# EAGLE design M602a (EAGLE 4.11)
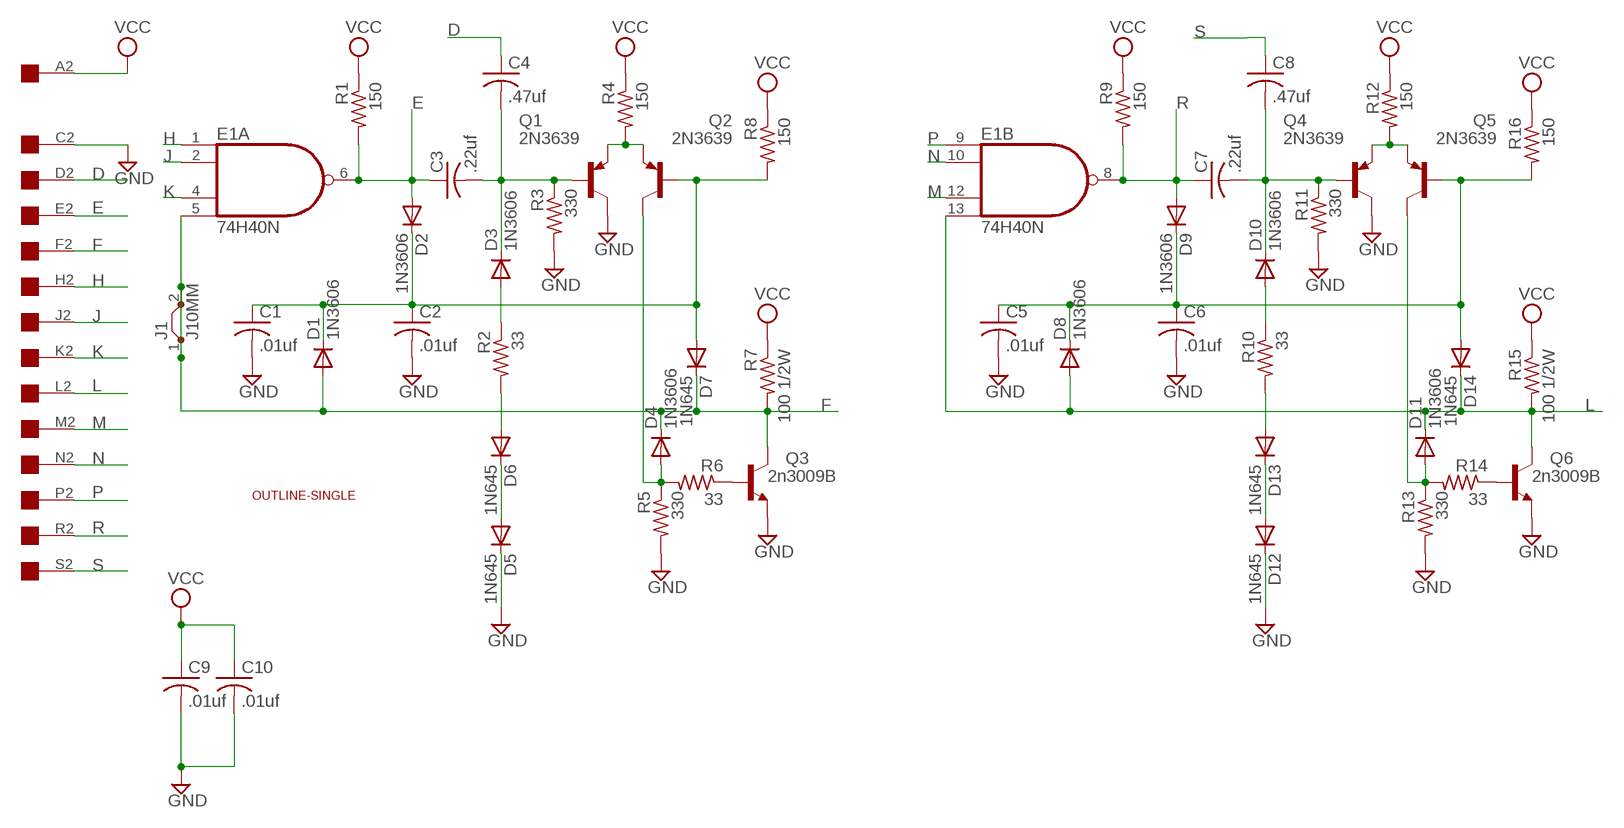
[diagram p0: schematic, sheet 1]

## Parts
C1  .01uf  C-US050-025X075  [C050-025X075]
C2  .01uf  C-US050-025X075  [C050-025X075]
C3  .22uf  C-US050-025X075  [C050-025X075]
C4  .47uf  C-US050-025X075  [C050-025X075]
C5  .01uf  C-US050-025X075  [C050-025X075]
C6  .01uf  C-US050-025X075  [C050-025X075]
C7  .22uf  C-US050-025X075  [C050-025X075]
C8  .47uf  C-US050-025X075  [C050-025X075]
C9  .01uf  C-US050-025X075  [C050-025X075]
C10  .01uf  C-US050-025X075  [C050-025X075]
D1  1N3606  1N4004  [DO41-10]
D2  1N3606  1N4004  [DO41-10]
D3  1N3606  1N4004  [DO41-10]
D4  1N3606  1N4004  [DO41-10]
D5  1N645  1N4004  [DO41-10]
D6  1N645  1N4004  [DO41-10]
D7  1N645  1N4004  [DO41-10]
D8  1N3606  1N4004  [DO41-10]
D9  1N3606  1N4004  [DO41-10]
D10  1N3606  1N4004  [DO41-10]
D11  1N3606  1N4004  [DO41-10]
D12  1N645  1N4004  [DO41-10]
D13  1N645  1N4004  [DO41-10]
D14  1N645  1N4004  [DO41-10]
E1  74H40N  74LS20N  [DIL14]
J1  J10MM  [10]
Q1  2N3639  2N5415  [TO39]
Q2  2N3639  2N5415  [TO39]
Q3  2n3009B  2N1711  [TO39]
Q4  2N3639  2N5415  [TO39]
Q5  2N3639  2N5415  [TO39]
Q6  2n3009B  2N1711  [TO39]
R1  150  R-US_0207/10  [0207/10]
R2  33  R-US_0207/10  [0207/10]
R3  330  R-US_0207/10  [0207/10]
R4  150  R-US_0207/10  [0207/10]
R5  330  R-US_0207/10  [0207/10]
R6  33  R-US_0207/10  [0207/10]
R7  100 1/2W  R-US_0207/10  [0207/10]
R8  150  R-US_0207/10  [0207/10]
R9  150  R-US_0207/10  [0207/10]
R10  33  R-US_0207/10  [0207/10]
R11  330  R-US_0207/10  [0207/10]
R12  150  R-US_0207/10  [0207/10]
R13  330  R-US_0207/10  [0207/10]
R14  33  R-US_0207/10  [0207/10]
R15  100 1/2W  R-US_0207/10  [0207/10]
R16  150  R-US_0207/10  [0207/10]
U$1  EDGE-1  [EDGE-CON1]
U$2  OUTLINE-SINGLE  [SINGLE]

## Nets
D: C4.1 U$1.D2
E: C3.1 D2.A E1.6(A:O) R1.2 U$1.E2
F: D1.A D4.C D7.C E1.5(A:I3) J1.1 J1.2 Q3.3(C) R7.2 U$1.F2
GND: C1.2 C2.2 C5.2 C6.2 C9.2 C10.2 D5.C D12.C Q1.3(C) Q3.1(E) Q4.3(C) Q6.1(E) R3.2 R5.2 R11.2 R13.2 U$1.C2
H: E1.1(A:I0) U$1.H2
J: E1.2(A:I1) U$1.J2
K: E1.4(A:I2) U$1.K2
L: D8.A D11.C D14.C E1.13(B:I3) Q6.3(C) R15.2 U$1.L2
M: E1.12(B:I2) U$1.M2
N: E1.10(B:I1) U$1.N2
N$1: C1.1 C2.1 D1.C D2.C D7.A Q2.2(B) R8.2
N$2: D3.A R2.1
N$3: D10.A R10.1
N$4: C3.2 C4.2 D3.C Q1.2(B) R3.1
N$5: Q1.1(E) Q2.1(E) R4.2
N$6: D4.A Q2.3(C) R5.1 R6.2
N$7: Q3.2(B) R6.1
N$8: D6.A R2.2
N$9: D5.A D6.C
N$10: C7.2 C8.2 D10.C Q4.2(B) R11.1
N$11: C5.1 C6.1 D8.C D9.C D14.A Q5.2(B) R16.2
N$13: D13.A R10.2
N$14: D12.A D13.C
N$15: Q6.2(B) R14.1
N$16: Q4.1(E) Q5.1(E) R12.2
N$17: D11.A Q5.3(C) R13.1 R14.2
P: E1.9(B:I0) U$1.P2
R: C7.1 D9.A E1.8(B:O) R9.2 U$1.R2
S: C8.1 U$1.S2
VCC: C9.1 C10.1 R1.1 R4.1 R7.1 R8.1 R9.1 R12.1 R15.1 R16.1 U$1.A2
Unconnected: U$1.B2 U$1.T2 U$1.U2 U$1.V2

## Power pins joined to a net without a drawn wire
GND: E1.7(P:GND)
VCC: E1.14(P:VCC)

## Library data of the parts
C1-C10 = rcl:C-US: CAPACITOR, American symbol
D1-D14 = diode:1N4004: DIODE
E1 = 74xx-us:74*20: Dual 4-input NAND gate
J1 = jumper:J: Bridge
Q1 Q2 Q4 Q5 = transistor-pnp:2N5415*: PNP Transistror
Q3 Q6 = transistor-npn:2N1711: NPN Transistor
R1-R16 = rcl:R-US_: RESISTOR, American symbol
U$1 = dec-con:EDGE-1: Single-Sided DEC Edge Connector -- (side 2)
U$2 = dec-con:OUTLINE-*: Board outlines for DEC boards.

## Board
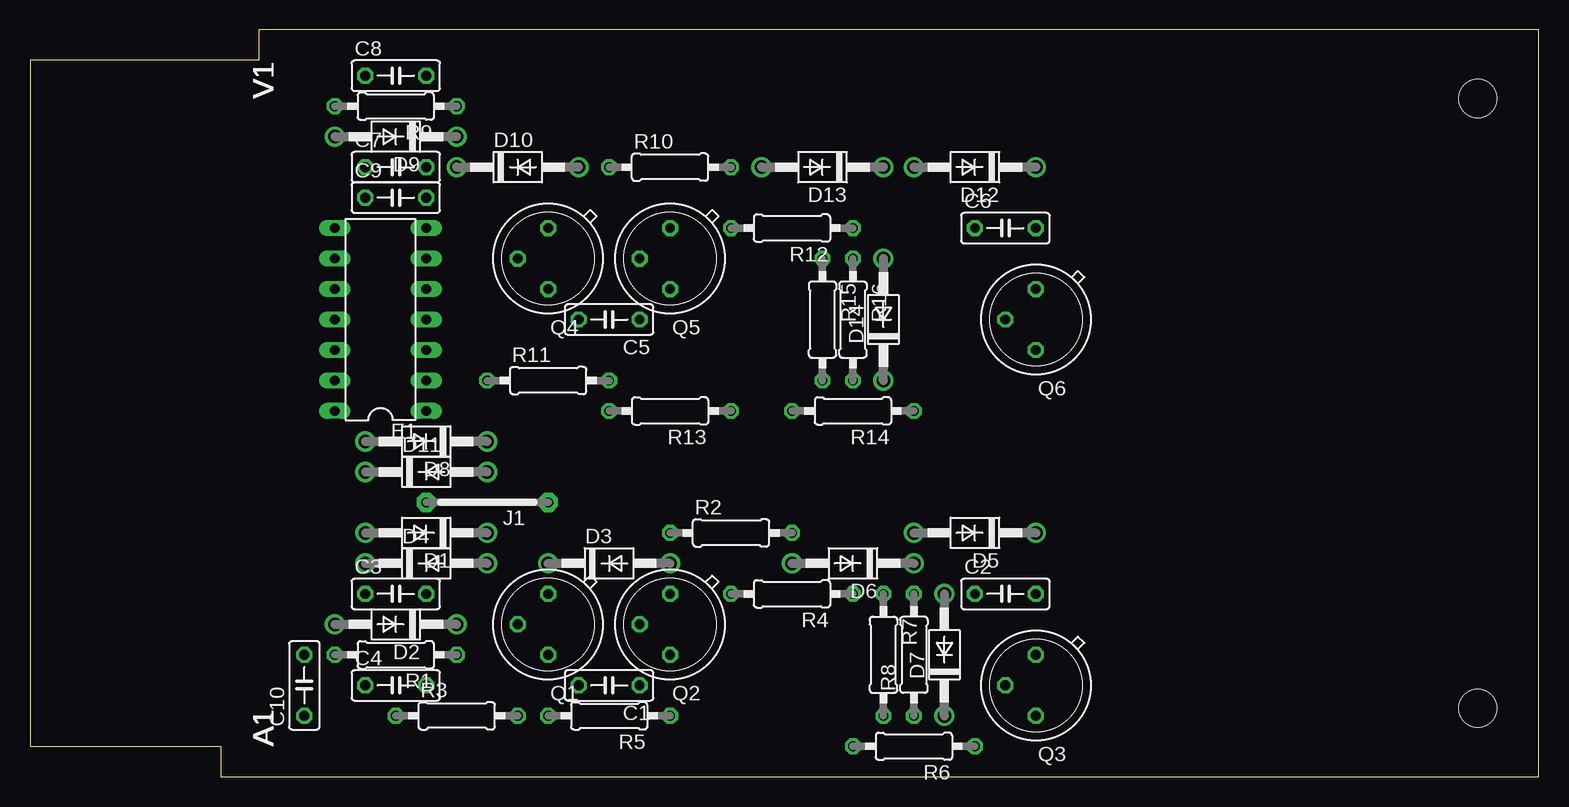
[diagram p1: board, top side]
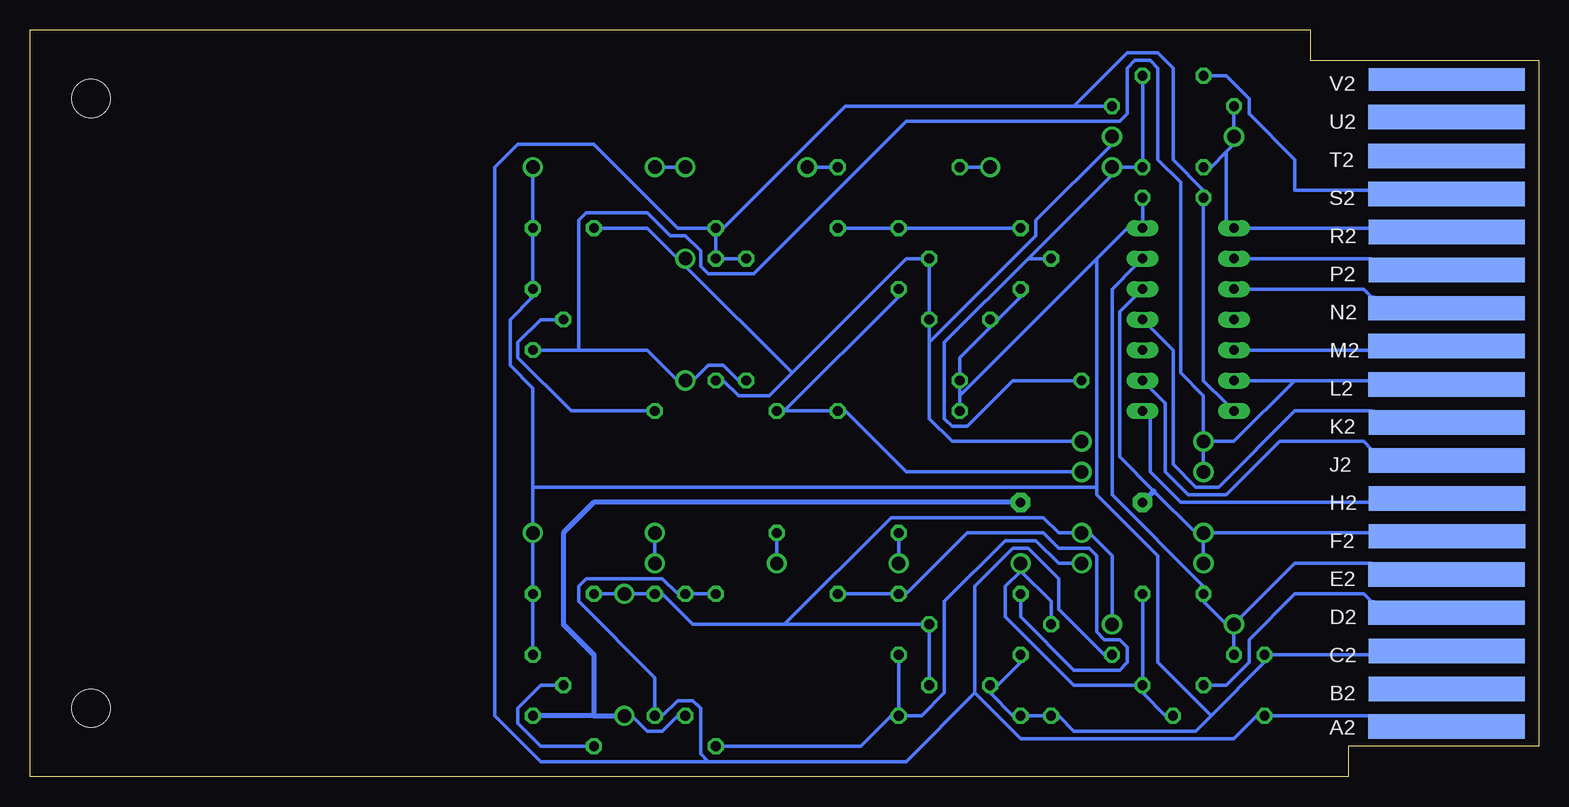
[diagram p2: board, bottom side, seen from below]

Size 125.73 x 62.23 mm. Coordinates in mm from the lower left corner, seen from the top.
Copper layers (1*16): Top 0.035mm / dielectric 1.5mm / Bottom 0.035mm
Design rules "10mils": minimum track width 12mil, minimum drill 28mil, track to track 10mil, track to pad 10mil, pad to pad 10mil, via to via 10mil, smd to smd 10mil, copper to edge 40mil, drill to drill 10mil, minimum pad ring 10mil, minimum via ring 8mil, stop-mask expansion 0mil, vias tented up to drill 0mil, thermal gap 10mil

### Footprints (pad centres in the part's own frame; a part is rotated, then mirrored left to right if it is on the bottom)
C050-025X075 = drill 0.813 octagon: 1 -2.54,0; 2 2.54,0
DO41-10 = drill 1.118 round: A 5.08,0; C -5.08,0
DIL14 = drill 0.813 long: 1 -7.62,-3.81; 2 -5.08,-3.81; 3 -2.54,-3.81; 4 0,-3.81; 5 2.54,-3.81; 6 5.08,-3.81; 7 7.62,-3.81; 8 7.62,3.81; 9 5.08,3.81; 10 2.54,3.81; 11 0,3.81; 12 -2.54,3.81; 13 -5.08,3.81; 14 -7.62,3.81
10 = drill 0.813 pad 1.6 octagon: 1 -5.08,0; 2 5.08,0
TO39 = drill 0.813 octagon: 1 0,-2.54; 2 2.54,0; 3 0,2.54
0207/10 = drill 0.813 octagon: 1 -5.08,0; 2 5.08,0
EDGE-CON1 = smd 13.017 x 2.032 bottom: A2 7.69,4.194; B2 7.668,7.328; C2 7.668,10.49; D2 7.693,13.665; E2 7.693,16.84; F2 7.642,20.041; H2 7.642,23.19; J2 7.668,26.34; K2 7.668,29.515; L2 7.693,32.69; M2 7.693,35.89; N2 7.693,39.04; P2 7.668,42.24; R2 7.668,45.39; S2 7.693,48.565; T2 7.693,51.74; U2 7.693,54.966 | smd 13.017 x 1.905 bottom: V2 7.668,58.102
SINGLE = hole 3.175: 120.65,56.515; 120.65,5.715

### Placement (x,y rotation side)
C1  48.26,7.62 180 top
C2  81.28,15.24 0 top
C3  30.48,15.24 0 top
C4  30.48,7.62 0 top
C5  48.26,38.1 180 top
C6  81.28,45.72 0 top
C7  30.48,50.8 0 top
C8  30.48,58.42 0 top
C9  30.48,48.26 0 top
C10  22.86,7.62 90 top
D1  33.02,20.32 180 top
D2  30.48,12.7 180 top
D3  48.26,17.78 0 top
D4  33.02,17.78 0 top
D5  78.74,20.32 180 top
D6  68.58,17.78 180 top
D7  76.2,10.16 90 top
D8  33.02,27.94 180 top
D9  30.48,53.34 180 top
D10  40.64,50.8 0 top
D11  33.02,25.4 0 top
D12  78.74,50.8 180 top
D13  66.04,50.8 180 top
D14  71.12,38.1 90 top
E1  29.21,38.1 90 top
J1  38.1,22.86 180 top
Q1  43.18,12.7 180 top
Q2  53.34,12.7 180 top
Q3  83.82,7.62 180 top
Q4  43.18,43.18 180 top
Q5  53.34,43.18 180 top
Q6  83.82,38.1 180 top
R1  30.48,10.16 180 top
R2  58.42,20.32 0 top
R3  35.56,5.08 0 top
R4  63.5,15.24 180 top
R5  48.26,5.08 180 top
R6  73.66,2.54 180 top
R7  71.12,10.16 270 top
R8  73.66,10.16 90 top
R9  30.48,55.88 180 top
R10  53.34,50.8 0 top
R11  43.18,33.02 0 top
R12  63.5,45.72 180 top
R13  53.34,30.48 180 top
R14  68.58,30.48 180 top
R15  66.04,38.1 270 top
R16  68.58,38.1 270 top
U$1  0,0 0 top
U$2  0,0 0 top

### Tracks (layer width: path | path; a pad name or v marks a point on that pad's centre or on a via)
D
  Bottom 0.305: C4.1 27.31,7.62 26.04,7.62 24.13,9.53 24.13,11.43 20.32,15.24 14.61,15.24 13.97,14.61 U$1.D2
E
  Bottom 0.305: R1.2 25.4,10.79 25.4,12.06 D2.A | D2.A 26.04,12.7 27.94,14.61 C3.1 27.94,15.88 35.56,23.5 35.56,40.64 33.66,42.55 E1.6 | D2.A 20.32,17.78 13.97,17.78 U$1.E2
F
  Top 0.406: J1.2 J1.1
  Bottom 0.305: R7.2 71.76,5.08 73.03,3.81 74.3,3.81 75.57,5.08 D7.C | D1.A 27.31,20.32 20.32,20.32 13.97,20.32 U$1.F2 | E1.5 33.66,40.01 34.93,38.73 34.93,26.67 32.07,23.81 28.58,20.32 D1.A | D4.C 27.94,18.41 27.94,19.68 D1.A
  Bottom 0.406: 78.74,5.08 78.74,10.16 81.28,12.7 81.28,20.32 78.74,22.86 J1.1 | 32.07,23.81 32.26,23.62 J1.2 | 78.74,5.08 D7.C | 78.74,5.08 Q3.3
GND
  Bottom 0.305: Q3.1 83.82,10.79 83.82,14.61 C2.2 83.82,15.88 83.82,19.68 D5.C 83.82,20.95 83.82,23.5 83.82,24.13 | D12.C 83.82,50.16 83.82,46.35 C6.2 83.82,45.09 83.82,41.27 Q6.1 83.82,40.01 85.73,38.1 85.73,34.29 83.82,32.38 83.82,24.13 | Q1.3 43.18,9.53 45.09,7.62 C1.2 45.72,6.99 43.82,5.08 R5.2 42.55,5.08 41.28,5.08 R3.2 40.01,5.08 38.74,3.81 28.58,3.81 27.31,5.08 | 27.31,5.08 22.86,9.53 C10.2 22.23,10.16 20.32,10.16 13.97,10.16 U$1.C2 | C9.2 33.02,47.62 33.02,46.35 E1.7 34.29,45.72 36.83,43.18 | 48.26,31.75 48.26,32.38 R11.2 48.26,33.66 48.26,34.92 45.72,37.47 C5.2 45.09,38.1 43.18,40.01 Q4.3 | 48.26,31.75 48.26,31.11 R13.2 | 36.83,43.18 48.26,31.75 | 27.31,5.08 31.75,9.53 31.75,18.41 36.83,23.5 36.83,24.13 | 36.83,24.13 36.83,43.18 | 36.83,24.13 83.82,24.13
H
  Bottom 0.305: E1.1 32.39,29.84 32.39,25.4 29.85,22.86 20.32,22.86 13.97,22.86 U$1.H2
J
  Bottom 0.305: E1.2 32.39,32.38 31.12,31.11 31.12,25.4 29.21,23.5 26.04,23.5 21.59,27.94 20.32,27.94 14.61,27.94 13.97,27.3 U$1.J2
K
  Bottom 0.305: E1.4 32.39,37.47 30.48,35.56 30.48,26.04 28.58,24.13 26.67,24.13 20.32,30.48 13.97,30.48 U$1.K2
L
  Bottom 0.305: D11.C 27.94,26.04 27.94,27.3 D8.A | 20.32,33.02 24.13,33.02 E1.13 | 20.32,33.02 25.4,27.94 27.31,27.94 D8.A | R15.2 66.68,33.02 67.95,34.29 69.22,34.29 70.49,33.02 D14.C 71.76,33.02 74.3,35.56 80.01,35.56 | 80.01,35.56 83.19,35.56 Q6.3 | 80.01,35.56 80.01,46.35 79.38,46.99 74.3,46.99 72.39,45.09 71.12,45.09 69.85,43.81 69.85,42.55 69.22,41.91 65.41,41.91 52.71,54.61 34.93,54.61 34.29,55.24 34.29,59.05 33.66,59.69 32.39,59.69 31.75,59.05 31.75,51.44 29.85,49.53 29.85,33.66 27.94,31.75 27.94,28.57 D8.A | 20.32,33.02 13.97,33.02 U$1.L2
M
  Bottom 0.305: E1.12 24.13,35.56 20.32,35.56 13.97,35.56 U$1.M2
N
  Bottom 0.305: E1.10 24.13,40.64 20.32,40.64 14.61,40.64 13.97,40.01 U$1.N2
N$1
  Bottom 0.305: D2.C 35.56,13.34 35.56,18.41 37.47,20.32 D1.C 38.74,20.32 40.01,20.32 41.28,21.59 53.98,21.59 62.87,12.7 | C1.1 50.8,8.26 50.8,12.06 Q2.2 51.44,12.7 62.87,12.7 | C2.1 78.11,15.24 76.84,15.24 D7.A 75.57,15.24 74.3,15.24 R8.2 73.03,15.24 70.49,12.7 62.87,12.7
N$2
  Bottom 0.305: R2.1 53.34,19.68 53.34,18.41 D3.A
N$3
  Bottom 0.305: R10.1 47.63,50.8 46.36,50.8 D10.A
N$4
  Bottom 0.305: 43.18,17.14 40.64,14.61 40.64,13.34 Q1.2 | 43.18,17.14 D3.C 43.18,17.14 | R3.1 31.12,5.08 33.02,6.99 C4.2 | C3.2 33.02,14.61 33.02,8.26 C4.2 | 43.18,17.14 44.45,15.88 44.45,13.34 38.74,7.62 33.66,7.62 C4.2
N$5
  Bottom 0.305: Q1.1 43.18,14.61 43.18,13.34 38.74,8.89 34.93,8.89 34.29,9.53 34.29,10.79 34.93,11.43 36.2,11.43 36.83,12.06 36.83,18.41 37.47,19.05 40.01,19.05 41.28,20.32 47.63,20.32 52.71,15.24 Q2.1 53.98,15.24 57.79,15.24 R4.2
N$6
  Bottom 0.305: R5.1 53.34,5.71 53.34,9.53 Q2.3 | R6.2 67.95,2.54 56.52,2.54 53.98,5.08 R5.1 | D4.A 38.74,17.78 40.01,17.78 41.91,19.68 44.45,19.68 49.53,14.61 49.53,6.99 51.44,5.08 52.71,5.08 R5.1
N$7
  Bottom 0.305: R6.1 79.38,2.54 83.19,2.54 85.09,4.45 85.09,5.71 83.19,7.62 81.92,7.62 Q3.2
N$8
  Bottom 0.305: R2.2 63.5,19.68 63.5,18.41 D6.A
N$9
  Bottom 0.305: D6.C 73.66,18.41 73.66,19.68 D5.A
N$10
  Bottom 0.305: C8.2 33.02,57.78 33.02,51.44 C7.2 33.66,50.8 34.93,50.8 D10.C 35.56,50.16 42.55,43.18 | 42.55,43.18 49.53,36.2 49.53,29.84 48.9,29.21 47.63,29.21 43.82,33.02 38.74,33.02 R11.1 | 42.55,43.18 41.28,43.18 Q4.2
N$11
  Bottom 0.305: C6.1 78.11,45.72 74.3,45.72 71.76,43.18 D14.A 71.12,42.55 62.23,33.66 | 62.23,33.66 52.71,43.18 51.44,43.18 Q5.2 50.8,42.55 50.8,38.73 C5.1 50.8,37.47 50.8,36.2 | 62.23,33.66 64.14,31.75 66.68,31.75 67.95,33.02 R16.2 | 50.8,36.2 50.8,29.84 48.9,27.94 38.74,27.94 D8.C | 50.8,36.2 41.91,45.09 41.91,46.35 35.56,52.7 D9.C
N$13
  Bottom 0.305: R10.2 59.06,50.8 60.33,50.8 D13.A
N$14
  Bottom 0.305: D13.C 71.76,50.8 73.03,50.8 D12.A
N$15
  Bottom 0.305: R14.1 74.3,30.48 80.65,30.48 85.09,34.92 85.09,36.2 83.19,38.1 81.92,38.1 Q6.2
N$16
  Bottom 0.305: Q4.1 43.82,45.72 52.71,45.72 Q5.1 53.98,45.72 57.79,45.72 R12.2
N$17
  Bottom 0.305: 62.87,30.48 59.06,30.48 R13.1 57.79,30.48 52.71,25.4 38.74,25.4 D11.A | 62.87,30.48 R14.2 62.87,30.48 | 62.87,30.48 53.34,40.01 Q5.3
P
  Bottom 0.305: E1.9 24.13,43.18 20.32,43.18 13.97,43.18 U$1.P2
R
  Bottom 0.305: 26.04,52.07 25.4,52.7 D9.A 25.4,53.98 25.4,55.24 R9.2 | 26.04,52.07 27.31,50.8 C7.1 | 26.04,52.07 26.04,46.35 E1.8 24.13,45.72 20.32,45.72 13.97,45.72 U$1.R2
S
  Bottom 0.305: C8.1 27.31,58.42 26.04,58.42 24.13,56.52 24.13,55.24 20.32,51.44 20.32,48.9 13.97,48.9 U$1.S2
VCC
  Bottom 0.305: E1.14 26.04,31.11 27.94,33.02 27.94,47.62 C9.1 27.94,48.9 30.48,51.44 30.48,59.05 31.75,60.33 34.29,60.33 38.74,55.88 | R15.1 66.68,43.18 67.95,43.18 R16.1 68.58,43.81 68.58,45.09 R12.1 | 38.74,55.88 57.79,55.88 67.95,45.72 R12.1 | 38.74,55.88 36.2,55.88 R9.1 | R4.1 69.22,15.24 70.49,15.24 R7.1 71.76,15.24 73.03,16.51 79.38,16.51 80.01,15.88 80.01,14.61 73.66,8.26 73.66,5.71 R8.1 73.03,5.08 71.76,6.35 70.49,6.35 69.85,5.71 69.85,1.91 69.22,1.27 | 46.99,6.99 46.99,15.88 43.82,19.05 42.55,19.05 40.01,16.51 40.01,13.97 36.2,10.16 R1.1 | 46.99,6.99 43.18,3.17 25.4,3.17 23.5,5.08 C10.1 22.23,5.08 20.32,5.08 13.97,5.08 U$1.A2 | 69.22,1.27 52.71,1.27 46.99,6.99 | 69.22,1.27 83.19,1.27 87,5.08 87,50.8 85.09,52.7 78.74,52.7 71.76,45.72 69.22,45.72 R12.1

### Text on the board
tNames: V1 | V1 | V1 | V1 | V1 | V1 | V1 | V1 | V1 | V1 | V1 | V1 | V1 | V1 | V1 | V1 | V1 | V1 | V1 | V1 | V1 | V1 | V1 | V1 | V1 | V1 | V1 | V1 | V1 | V1 | V1 | V1 | A1 | A1 | A1 | A1 | A1 | A1 | A1 | A1 | A1 | A1 | A1 | A1 | A1 | A1 | A1 | A1 | A1 | A1 | A1 | A1 | A1 | A1 | A1 | A1 | A1 | A1 | A1 | A1 | A1 | A1 | A1 | A1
